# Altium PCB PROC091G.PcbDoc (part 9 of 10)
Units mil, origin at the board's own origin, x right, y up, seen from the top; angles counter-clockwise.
Board outline 4538.11 x 994.94 mil, 8 copper layers (Top Layer, GND1, Sig1, PWR1, PWR2, Sig2, GND2, Bottom Layer), stack 59.155 mil thick; 446 components, 329 nets, 5050 pads, 868 vias.
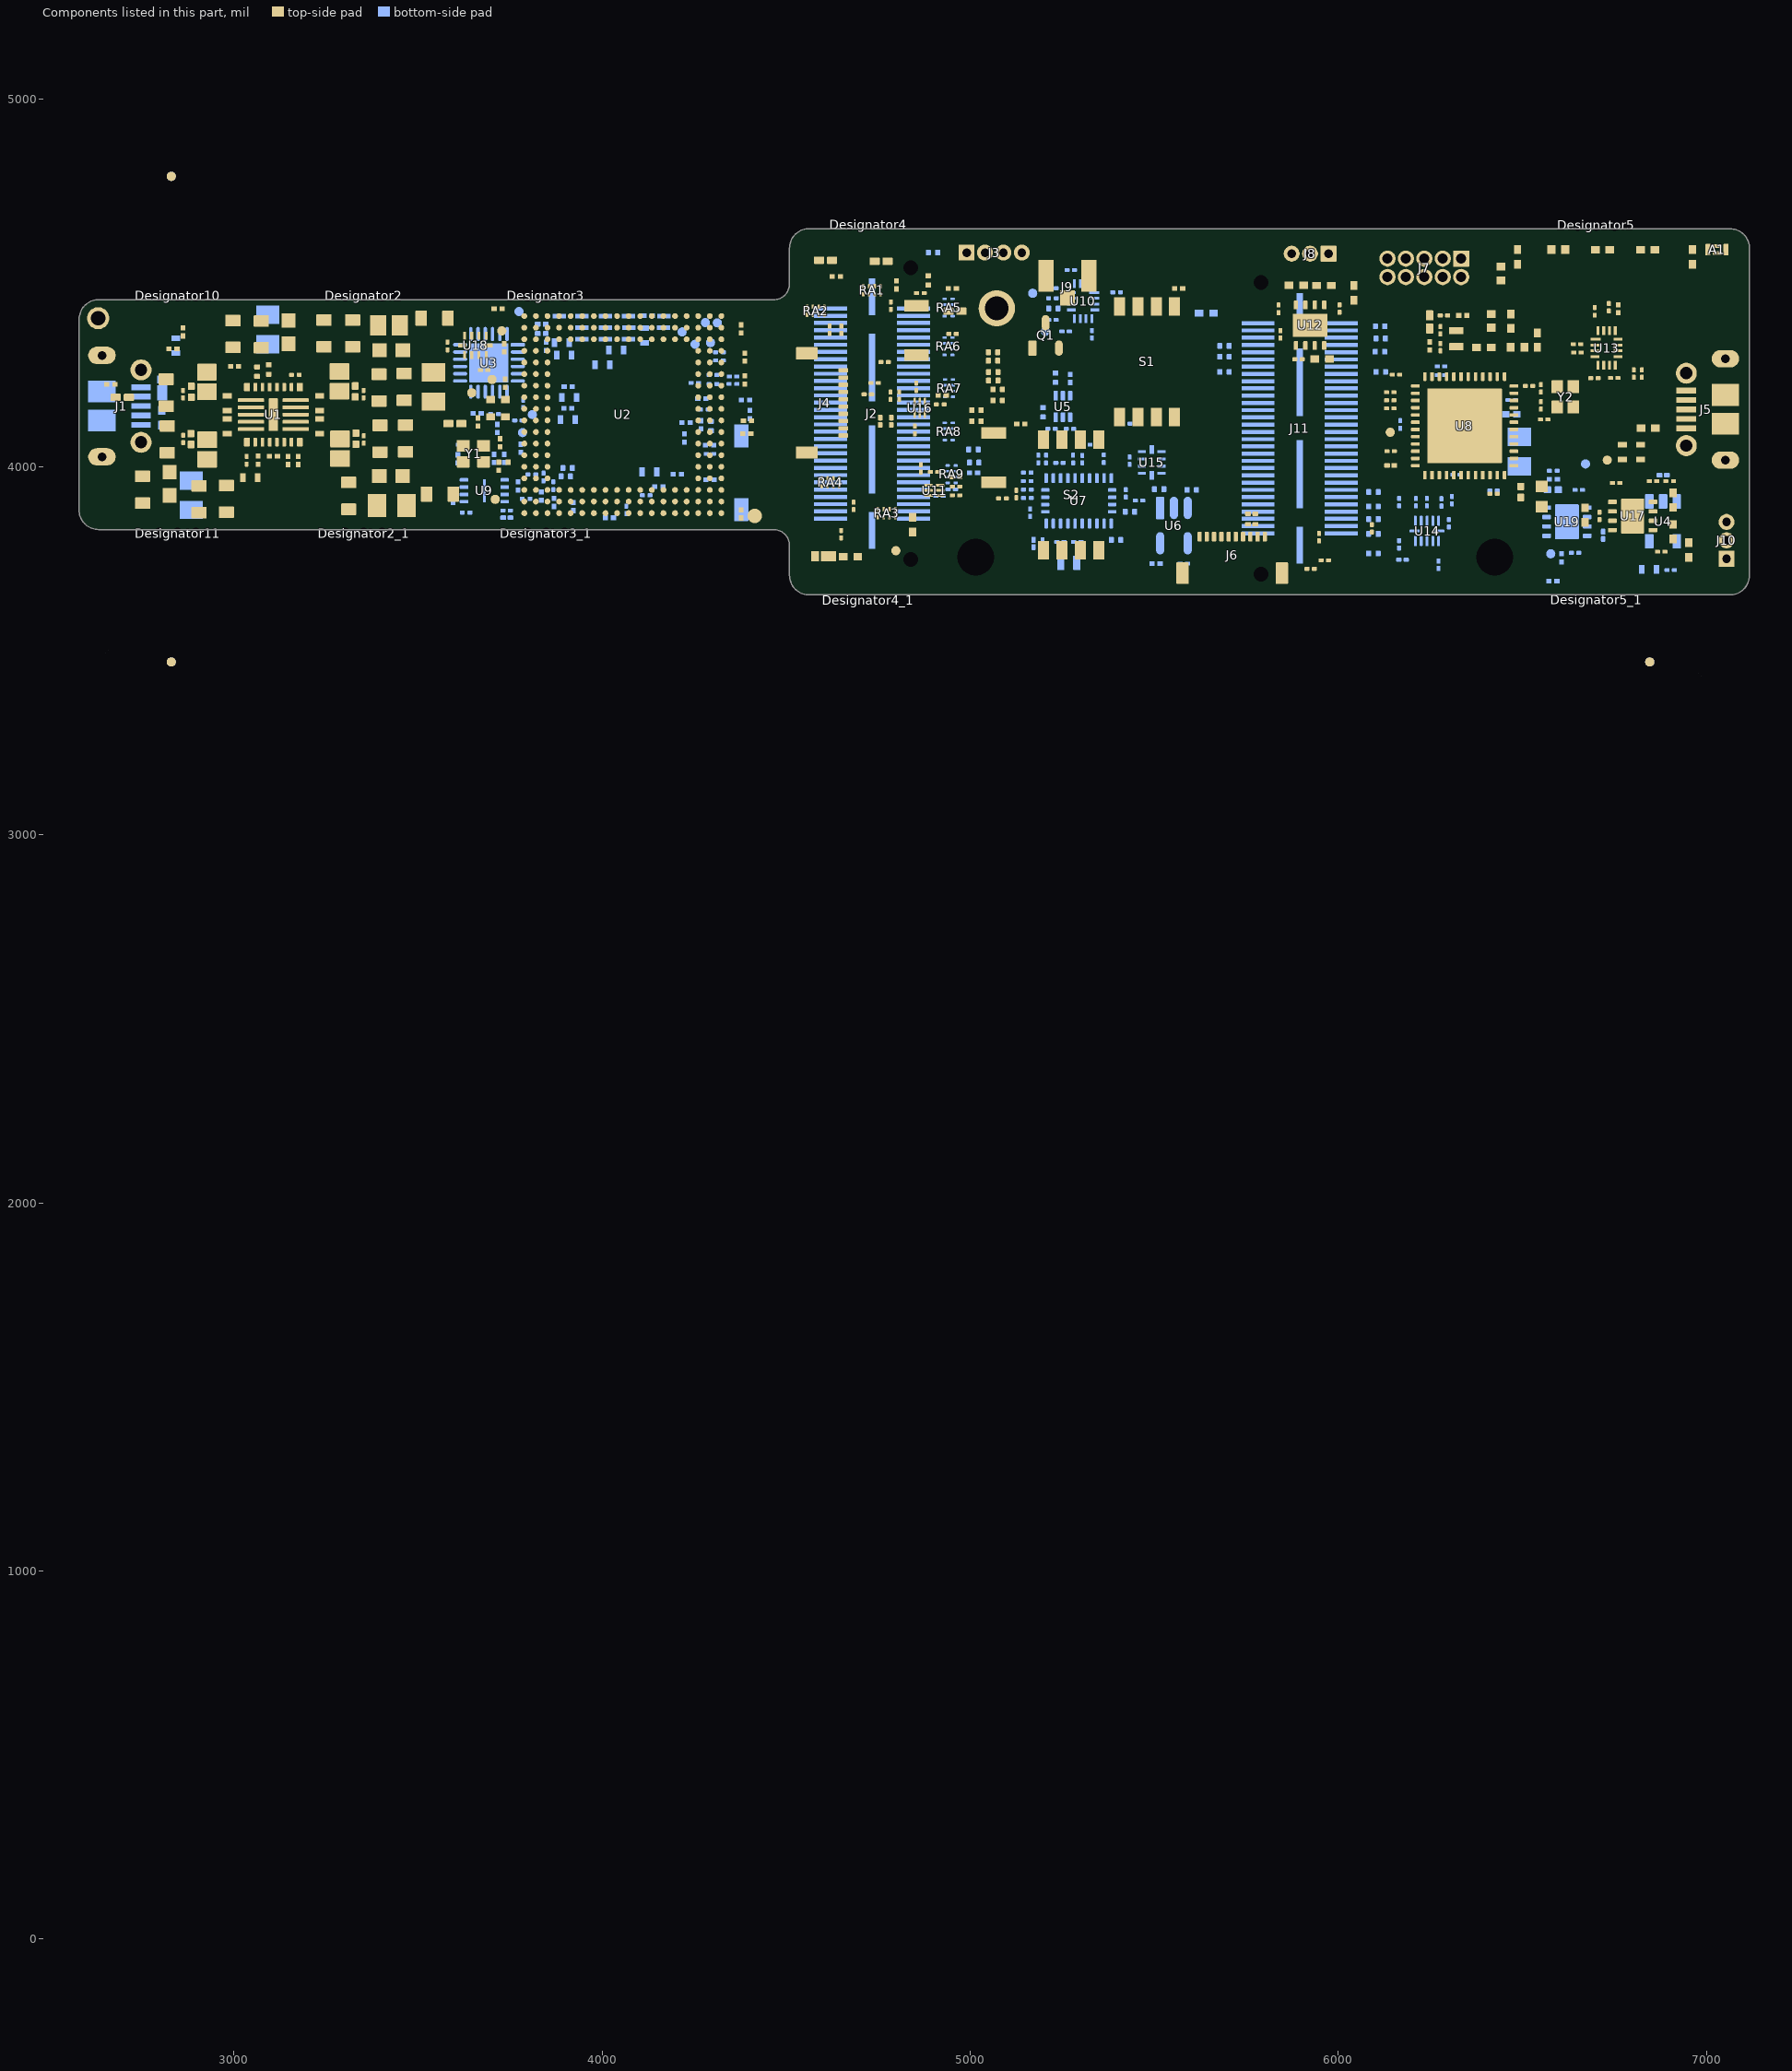
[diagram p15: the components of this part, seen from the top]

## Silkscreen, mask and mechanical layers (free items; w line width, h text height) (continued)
M10 Fab Notes:
  drawing of 275 lines, arcs and shapes, not listed
  text "2" at 3215,8061 h70
  text "1" at 739.84,8036.5 h70
  text "3" at 5724.84,8036.5 h70
  text "4" at 8231.51,8036.5 h70
  text "5" at 10730.5,8036.5 h70
  text "6" at 13235.5,8036.5 h70
  text "A" at -416.5,6893.5 h70
  text "A" at 14383.5,6893.5 h70
  text "DESIGN INFORMATION" at 12391.15,6364.21 h60
  text "3.5" at 12769.13,6238.04 h60
  text "MIN. TRACK WIDTH:" at 11746.59,6232.09 h60
  text "MIL" at 12997.59,6232.09 h60
  text "MIN. CLEARANCE:" at 11746.59,6107.96 h60
  text "3.5" at 12782.83,6107.96 h60
  text "MIL" at 12997.59,6107.96 h60
  text "MIN. VIA PAD SIZE:" at 11746.59,5983.83 h60
  text "18" at 12812.84,5983.84 h60
  text "MIL" at 12997.59,5983.83 h60
  text "0.05mm (2MIL)" at 12441.59,5853.93 h60
  text "MINIMUM ANNULAR RING" at 11417.36,5845.71 h60
  text "EXTERNAL" at 13149.59,5845.71 h60
  text "PER" at 11617.36,5735.58 h60
  text "IPC-D-275 CLASS 2 LEVEL C" at 11837.36,5735.58 h60
  text "MIL, HOLES" at 13325.59,5635.11 h60
  text "+/-" at 12933.13,5626.52 h60
  text "+/-" at 13787.13,5626.52 h60
  text "REGISTRATION TOLERANCES:" at 11417.36,5625.46 h60
  text "METAL" at 12617.13,5625.46 h60
  text "5" at 13193.33,5625.46 h60
  text "3" at 14026.33,5625.46 h60
  text "MIL" at 14142.59,5625.46 h60
  text "HOLE SIZE TOLERANCE (UNLESS OTHERWISE SPECIFIED):" at 11417.36,5527.14 h60
  text "+/-" at 13787.13,5524.27 h60
  text "3" at 14026.33,5523.21 h60
  text "MIL" at 14142.59,5523.2 h60
  text "MATERIAL:" at 11342.59,5385.56 h60
  text "FR-4 High Tg" at 12329.03,5257.03 h60
  text "X" at 12176.59,5254.04 h60
  text "FR-408" at 11763.59,5244.53 h60
  text "OTHER" at 13251.59,5244.53 h60
  text "64 MIL (1.62mm) +/-10%" at 12083.69,5101.5 h60
  text "X" at 11963.59,5099.04 h60
  text "THICKNESS:" at 11417.36,5093.27 h60
  text "OTHER" at 13368.59,5093.27 h60
  text "TOLERANCE:" at 11417.36,4954.96 h60
  text "X" at 12265.59,4954.96 h60
  text "ANSI IPC-6012 TYPE 3 CLASS 2" at 12443.6,4954.96 h60
  text "OTHER +/-" at 12443.59,4810.77 h60
  text "BOW & TWIST:" at 11417.36,4665.58 h60
  text "X" at 12265.59,4665.58 h60
  text "ANSI IPC-6012 TYPE 3 CLASS 2" at 12443.6,4665.58 h60
  text "OTHER +/-" at 12443.59,4518.89 h60
  text "B" at -416.5,4513.5 h70
  text "B" at 14383.5,4513.5 h70
  text "DRILLING:" at 11342.59,4388.27 h60
  text "NC_DRILL FILES" at 13103.59,4283.08 h60
  text "REFERENCE:" at 11417.36,4279.14 h60
  text "X" at 12074.59,4279.04 h60
  text "AS SHOWN" at 12252.59,4279.14 h60
  text "X" at 12975.59,4279.14 h60
  text "OTHER" at 13401.59,4136.89 h60
  text "PTH COPPER THICKNESS:" at 11417.03,4133.36 h60
  text "X" at 12556.27,4133.36 h60
  text "20-30 um" at 12684.27,4133.36 h60
  text "BOARD FINISH:" at 11342.59,3985.76 h60
  text "SILKSCREEN:" at 11497.81,3875.64 h60
  text "X" at 12455.59,3875.64 h60
  text "TOP" at 12572.59,3875.64 h60
  text "X" at 12965.59,3875.64 h60
  text "BOTTOM" at 13083.59,3875.64 h60
  text "SILKSCREEN COLOR:" at 11497.81,3720.45 h60
  text "X" at 12454.59,3720.45 h60
  text "WHITE" at 12572.59,3720.45 h60
  text "OTHER" at 13083.59,3720.45 h60
  text "X" at 12585.59,3577 h60
  text "RED" at 12703.59,3577 h60
  text "OTHER" at 13321.59,3577 h60
  text "SOLDER RESIST COLOR:" at 11497.81,3570.13 h60
  text "X" at 12585.59,3422.75 h60
  text "MATTE" at 12703.59,3422.75 h60
  text "SEMI-GLOSS" at 13321.13,3422.11 h60
  text "IMMERSION GOLD (ENIG)" at 12403.59,3249.98 h60
  text "ENEPIG" at 13741.13,3242.75 h60
  text "SURFACE FINISH:" at 11342.59,3241.75 h60
  text "X" at 12225.59,3241.75 h60
  text "IMM. TIN/SILVER OR EQUIV" at 11672.13,3104.44 h60
  text "OTHER" at 13103.59,3100.5 h60
  text "ARRAY/PANEL:" at 11342.59,2945.12 h60
  text "CUT AND TRIM PER M1 BOARD OUTLINE" at 12403.59,2936.9 h60
  text "X" at 12215,2804 h60
  text "N.C. ROUTE" at 12403.59,2800.94 h60
  text "V. SCORE" at 13269.59,2800.94 h60
  text "CERTIFICATION:" at 11342.59,2671.81 h60
  text "MATERIALS AND WORKMANSHIP FOR ALL PCBS" at 12067.59,2671.81 h60
  text "TO MEET OR EXCEED THE REQUIREMENTS OF:" at 12067.59,2577.75 h60
  text "X" at 11705.1,2449.12 h60
  text "ANSI IPC-A-600F CLASS ->" at 11833.09,2449.12 h60
  text "X" at 13481.1,2449.12 h60
  text "2" at 13591.09,2449.12 h60
  text "1" at 13276.09,2447.62 h60
  text "3" at 13945.09,2447.62 h60
  text "X" at 12517.1,2301.43 h60
  text "RoHS" at 12645.09,2301.43 h60
  text "OTHER" at 13289.49,2301.43 h60
  text "PER ORDER" at 13686.55,2301.43 h60
  text "ALL BOARDS MUST MEET OR EXCEED UL94-V0 REQUIREMENTS." at 11370.13,2147.6 h60
  text "C" at -416.5,2138.5 h70
  text "C" at 14383.5,2138.5 h70
  text "PCB MUST BEAR THE UL94V-0 UL REGISTERED MATERIAL ID NUMBER" at 11370.13,2031.54 h60
  text "ADDITIONAL REQUIREMENTS:" at 11342.59,1862.12 h60
  text "MICROSECTION:" at 11417.36,1754.99 h60
  text "YES" at 12323.09,1754.99 h60
  text "REQUIRED" at 13184.59,1610.66 h60
  text "BARE BOARD ELEC. TEST:" at 11417.36,1607.8 h60
  text "NONE" at 12723.09,1607.8 h60
  text "X" at 13066.59,1607.8 h60
  text "PER ORDER" at 13776.59,1607.8 h60
  text "IMPEDANCE SPECIFICATIONS" at 28.98,1507.25 h82.24
  text "IMPEDANCE SPECIFICATIONS" at 28.98,1507.25 h82.24
  text "XX MIL VIAS REQUIRE NON-CONDUCTIVE FILL AND PLANARIZE" at 11585.51,1402.85 h59
  text "XX MIL VIAS REQUIRE CONDUCTIVE FILL AND PLANARIZE" at 11593.51,1298.88 h60
  text "SL#" at -82.05,1219.4 h82.24
  text "SL#" at -82.05,1219.4 h82.24
  text "TYPE" at 1057,1219.4 h82.24
  text "TYPE" at 1057,1219.4 h82.24
  text "LAYER" at 2257.73,1219.4 h82.24
  text "LAYER" at 2257.73,1219.4 h82.24
  text "TRACEWIDTH(Mils)" at 2944.45,1219.4 h82.24
  text "TRACEWIDTH(Mils)" at 2944.45,1219.4 h82.24
  text "SPACING(Mils)" at 4297.33,1219.4 h82.24
  text "SPACING(Mils)" at 4297.33,1219.4 h82.24
  text "IMPEDANCE(Ohms)" at 5444.61,1219.4 h82.24
  text "IMPEDANCE(Ohms)" at 5444.61,1219.4 h82.24
  text "REF LAYER" at 6711.13,1219.4 h82.24
  text "REF LAYER" at 6711.13,1219.4 h82.24
  text "X" at 11460.14,1142.4 h60
  text "OUTER XX MIL TRACES REQUIRE 50 OHM SINGLE-ENDED IMPEDANCE" at 11592.52,1135.49 h58
  text "L02,L07" at 6867.2,1037.35 h82.24
  text "L1,L8" at 2287.52,1034.24 h82.24
  text "5.50" at 3435.43,1031.07 h82.24
  text "---" at 4689.62,1031.07 h82.24
  text "50" at 5902.69,1031.07 h82.24
  text "MICROSTRIP" at 236.71,1021.53 h82.24
  text "01" at -49.15,1013.79 h82.24
  text "01" at -49.15,1013.79 h82.24
  text "X" at 11462.02,980.86 h60
  text "LAYER 2 & 3 (INNER LAYERS) XX MIL WIDE, XX MIL SPACE / TRACES REQUIRE 100 OHM DIFFERENTIAL IMPEDANCE" at 11584.52,899.78 h60
  text "L07" at 6867.75,897.96 h82.24
  text "4.5" at 4748.83,894.54 h82.24
  text "EDGE COUPLED MICROSTRIP" at 237.95,889.73 h82.24
  text "L8" at 2287.52,890.32 h82.24
  text "4.00" at 3435.43,887.14 h82.24
  text "90" at 5902.69,887.14 h82.24
  text "02" at -48.99,880.83 h82.24
  text "7" at 4794.36,757.36 h82.24
  text "L02,L07" at 6867.2,749.5 h82.24
  text "EDGE COUPLED MICROSTRIP" at 237.95,746.32 h82.24
  text "L1,L8" at 2287.52,746.4 h82.24
  text "4.00" at 3435.43,743.22 h82.24
  text "100" at 5902.69,743.22 h82.24
  text "03" at -48.99,736.91 h82.24
  text "6.1" at 4794.36,613.43 h82.24
  text "L03" at 6867.2,605.58 h82.24
  text "EDGE COUPLED MICROSTRIP" at 237.95,602.4 h82.24
  text "L1" at 2287.52,602.47 h82.24
  text "4.00" at 3435.43,599.3 h82.24
  text "120" at 5902.69,599.3 h82.24
  text "04" at -48.99,592.99 h82.24
  text "L02/04,L05/07" at 6598.31,468.41 h82.24
  text "STRIPLINE" at 233.74,463.86 h82.24
  text "L3,L6" at 2290.85,462.34 h82.24
  text "4.2" at 3435.43,454.49 h82.24
  text "---" at 4689.62,454.49 h82.24
  text "50" at 5902.69,454.49 h82.24
  text "05" at -48.99,449.06 h82.24
  text "L6" at 2290.85,318.41 h82.24
  text "L05/07" at 6755.25,316.53 h82.24
  text "EDGE COUPLED STRIPLINE" at 235.82,316.19 h82.24
  text "6" at 4782.55,314.68 h82.24
  text "4.00" at 3435.43,310.57 h82.24
  text "90" at 5902.69,310.57 h82.24
  text "06" at -48.99,305.14 h82.24
  text "PROJECT TITLE:" at 11343.5,277.5 h45
  text "EDGE COUPLED STRIPLINE" at 233.74,178.91 h82.24
  text "L02/04" at 6755.25,177.53 h82.24
  text "L3" at 2290.85,174.49 h82.24
  text "8" at 4782.55,170.76 h82.24
  text "3.5" at 3435.43,166.65 h82.24
  text "100" at 5902.69,166.65 h82.24
  text "07" at -40.92,163.56 h82.24
  text ".PRJ_Title" at 11393.5,144.17 h70
  text "L1" at 2295.75,39.2 h82.24
  text "14.153" at 3373.6,37.65 h82.24
  text "50" at 5910.92,36.02 h82.24
  text "8.924" at 4721.96,31.51 h82.24
  text "L03" at 6878.95,28.02 h82.24
  text "COPLANAR" at 244.94,26.49 h82.24
  text "08" at -40.92,13.42 h82.24
  text "DESIGNED FOR:" at 11343.5,-23.5 h45
  text ".PRJ_Customer" at 11393.5,-163.5 h70
  text "D" at -416.5,-231.5 h70
  text "D" at 14383.5,-231.5 h70
  text "FILE NAME:" at 11343.5,-323.5 h45
  text ".PCB_File_Name_No_Path" at 11393.5,-443.5 h70
  text "Texas Instruments (TI) and/or its licensors do not warrant the accuracy or completeness of this specification" at 6374,-605.34 h45
  text "ENGINEER:" at 11343.5,-613.5 h45
  text "LAYOUT BY:" at 12848.5,-613.5 h45
  text "or any information contained therein. TI and/or its licensors do not warrant that this design will meet" at 6329.01,-718 h45
  text ".PRJ_Engineer" at 11393.5,-768.49 h70
  text ".PCB_Layout" at 12899,-768.49 h70
  text "the specifications, will be suitable for your application or fit for any particular purpose, or will operate in" at 6329.01,-830.67 h45
  text ".Layer_Name" at 577,-858.49 h60
  text "ALTIUM DESIGNER VERSION:" at 12848.5,-923.5 h45
  text "an implementation. TI and/or its licensors do not warrant that the design is production worthy. You should" at 6329.01,-943.33 h45
  text "completely validate and test your design implementation to confirm the system functionality for your application." at 6374,-1056 h45
  text ".print_Scale" at 11393.5,-1056.83 h70
  text ".Application_BuildNumber" at 12899,-1056.83 h70
  text "1" at 739.84,-1263.5 h70
  text "2" at 3235.5,-1263.5 h70
  text "3" at 5724.84,-1263.5 h70
  text "4" at 8231.51,-1263.5 h70
  text "5" at 10730.5,-1263.5 h70
  text "6" at 13235.5,-1263.5 h70
M11 Gerber Information:
  lines w10: -288.5,-917.67 6311.5,-917.67 ; -288.5,-714.33 6313.5,-714.33 ; -288.5,-511 -288.5,-1121 3716.5,-1121 6313.5,-1121 6313.5,-511 -288,-511 -288,-1121 1287.5,-1121 ; 2176.5,-1121 2176.5,-511 ; 3443.5,-714.33 3443.5,-511 ; 4283.5,-714.33 4283.5,-511 ; 4905.5,-1127.5 4905.5,-924.67
  text "ALL ARTWORK VIEWED FROM TOP SIDE" at -228.5,-655.67 h60
  text "BOARD #:" at 2248,-655.67 h60
  text ".PRJ_Number" at 2793.5,-655.67 h60
  text "REV:" at 3638,-655.67 h60
  text ".PCB_Rev" at 3929.5,-655.67 h60
  text "SVN REV:" at 4476,-655.67 h60
  text ".VersionControl_RevNumber" at 4982,-655.67 h60
  text "LAYER NAME =" at -228.5,-858.49 h60
  text "TID #:" at 2248,-859 h60
  text ".TID" at 2793.5,-859 h60
  text "PLOT NAME =" at -228.5,-1064.34 h60
  text ".plot_File_Name" at 577,-1064.34 h60
  text "GENERATED    :" at 2250,-1064.34 h60
  text ".Print_Date" at 3119.5,-1064.34 h60
  text ".Print_Time" at 3848.5,-1064.34 h60
  text "TEXAS INSTRUMENTS" at 5113,-1064.34 h60
M12 Stackup:
  drawing of 659 lines, arcs and shapes, not listed
  text "Layer" at 7337.32,6608.67 h50.66
  text "Name" at 7686.51,6608.67 h50.66
  text "Material" at 8474.58,6608.67 h50.66
  text "Thickness" at 9203.57,6608.67 h50.66
  text "Constant" at 9755.32,6608.67 h50.66
  text "Board Layer Stack" at 10239.55,6608.67 h50.66
  text "1" at 7337.32,6507.36 h50.66
  text "Top Overlay" at 7686.51,6507.36 h50.66
  text "2" at 7337.32,6406.04 h50.66
  text "Top Solder" at 7686.51,6406.04 h50.66
  text "Solder Resist" at 8474.58,6406.04 h50.66
  text "2.00mil" at 9203.57,6406.04 h50.66
  text "4.4" at 9755.32,6406.04 h50.66
  text "3" at 7337.32,6304.73 h50.66
  text "Top Layer" at 7686.51,6304.73 h50.66
  text "Copper" at 8474.58,6304.73 h50.66
  text "1.85mil" at 9203.57,6304.73 h50.66
  text "4" at 7337.32,6203.42 h50.66
  text "Dielectric1" at 7686.51,6203.42 h50.66
  text "FR-4 High Tg" at 8474.58,6203.42 h50.66
  text "1.46mil" at 9203.57,6203.42 h50.66
  text "3.832" at 9755.32,6203.42 h50.66
  text "5" at 7337.32,6102.11 h50.66
  text "Dielectric 2" at 7686.51,6102.11 h50.66
  text "FR-4 High Tg" at 8474.58,6102.11 h50.66
  text "2.22mil" at 9203.57,6102.11 h50.66
  text "3.832" at 9755.32,6102.11 h50.66
  text "6" at 7337.32,6000.8 h50.66
  text "GND1" at 7686.51,6000.8 h50.66
  text "Copper" at 8474.58,6000.8 h50.66
  text "2.64mil" at 9203.57,6000.8 h50.66
  text "7" at 7337.32,5899.48 h50.66
  text "Dielectric3" at 7686.51,5899.48 h50.66
  text "FR-4 High Tg" at 8474.58,5899.48 h50.66
  text "4.00mil" at 9203.57,5899.48 h50.66
  text "4.4" at 9755.32,5899.48 h50.66
  text "8" at 7337.32,5798.17 h50.66
  text "Sig1" at 7686.51,5798.17 h50.66
  text "Copper" at 8474.58,5798.17 h50.66
  text "1.26mil" at 9203.57,5798.17 h50.66
  text "9" at 7337.32,5696.86 h50.66
  text "Dielectric4" at 7686.51,5696.86 h50.66
  text "FR-4 High Tg" at 8474.58,5696.86 h50.66
  text "3.16mil" at 9203.57,5696.86 h50.66
  text "4.13" at 9755.32,5696.86 h50.66
  text "10" at 7337.32,5595.55 h50.66
  text "Dielectric 5" at 7686.51,5595.55 h50.66
  text "FR-4 High Tg" at 8474.58,5595.55 h50.66
  text "3.16mil" at 9203.57,5595.55 h50.66
  text "4.13" at 9755.32,5595.55 h50.66
  text "11" at 7337.32,5494.24 h50.66
  text "Dielectric 6" at 7686.51,5494.24 h50.66
  text "FR-4 High Tg" at 8474.58,5494.24 h50.66
  text "3.16mil" at 9203.57,5494.24 h50.66
  text "4.13" at 9755.32,5494.24 h50.66
  text "12" at 7337.32,5392.92 h50.66
  text "PWR1" at 7686.51,5392.92 h50.66
  text "Copper" at 8474.58,5392.92 h50.66
  text "2.64mil" at 9203.57,5392.92 h50.66
  text "13" at 7337.32,5291.61 h50.66
  text "Dielectric7" at 7686.51,5291.61 h50.66
  text "FR-4 High Tg" at 8474.58,5291.61 h50.66
  text "8.00mil" at 9203.57,5291.61 h50.66
  text "4.41" at 9755.32,5291.61 h50.66
  text "14" at 7337.32,5190.3 h50.66
  text "PWR2" at 7686.51,5190.3 h50.66
  text "Copper" at 8474.58,5190.3 h50.66
  text "2.64mil" at 9203.57,5190.3 h50.66
  text "15" at 7337.32,5088.99 h50.66
  text "Dielectric8" at 7686.51,5088.99 h50.66
  text "FR-4 High Tg" at 8474.58,5088.99 h50.66
  text "3.18mil" at 9203.57,5088.99 h50.66
  text "4.13" at 9755.32,5088.99 h50.66
  text "16" at 7337.32,4987.67 h50.66
  text "Dielectric 9" at 7686.51,4987.67 h50.66
  text "FR-4 High Tg" at 8474.58,4987.67 h50.66
  text "3.18mil" at 9203.57,4987.67 h50.66
  text "4.13" at 9755.32,4987.67 h50.66
  text "17" at 7337.32,4886.36 h50.66
  text "Dielectric 10" at 7686.51,4886.36 h50.66
  text "FR-4 High Tg" at 8474.58,4886.36 h50.66
  text "3.18mil" at 9203.57,4886.36 h50.66
  text "4.13" at 9755.32,4886.36 h50.66
  text "18" at 7337.32,4785.05 h50.66
  text "Sig2" at 7686.51,4785.05 h50.66
  text "Copper" at 8474.58,4785.05 h50.66
  text "1.26mil" at 9203.57,4785.05 h50.66
  text "19" at 7337.32,4683.74 h50.66
  text "Dielectric11" at 7686.51,4683.74 h50.66
  text "FR-4 High Tg" at 8474.58,4683.74 h50.66
  text "4.00mil" at 9203.57,4683.74 h50.66
  text "4.4" at 9755.32,4683.74 h50.66
  text "20" at 7337.32,4582.43 h50.66
  text "GND2" at 7686.51,4582.43 h50.66
  text "Copper" at 8474.58,4582.43 h50.66
  text "2.64mil" at 9203.57,4582.43 h50.66
  text "21" at 7337.32,4481.11 h50.66
  text "Dielectric12" at 7686.51,4481.11 h50.66
  text "FR-4 High Tg" at 8474.58,4481.11 h50.66
  text "2.22mil" at 9203.57,4481.11 h50.66
  text "3.832" at 9755.32,4481.11 h50.66
  text "22" at 7337.32,4379.8 h50.66
  text "Dielectric 13" at 7686.51,4379.8 h50.66
  text "FR-4 High Tg" at 8474.58,4379.8 h50.66
  text "1.46mil" at 9203.57,4379.8 h50.66
  text "3.832" at 9755.32,4379.8 h50.66
  text "23" at 7337.32,4278.49 h50.66
  text "Bottom Layer" at 7686.51,4278.49 h50.66
  text "Copper" at 8474.58,4278.49 h50.66
  text "1.85mil" at 9203.57,4278.49 h50.66
  text "24" at 7337.32,4177.18 h50.66
  text "Bottom Solder" at 7686.51,4177.18 h50.66
  text "Solder Resist" at 8474.58,4177.18 h50.66
  text "2.00mil" at 9203.57,4177.18 h50.66
  text "4.4" at 9755.32,4177.18 h50.66
  text "25" at 7337.32,4075.87 h50.66
  text "Bottom Overlay" at 7686.51,4075.87 h50.66
  text ".Layer_Name" at 577,-858.49 h60
M13 Component Bodies Top:
  text ".Layer_Name" at 577,-858.49 h60
M14 Component Bodies Bottom:
  text ".Layer_Name" at 577,-858.49 h60
M15 Courtyards Top:
  text ".Layer_Name" at 577,-858.49 h60
M16 Courtyards Bottom:
  text ".Layer_Name" at 577,-858.49 h60
Drill Drawing:
  circle w10: c7611.94,1798.84 r16.58
  circle w10: c7611.94,1798.84 r27.63
  circle w10: c7611.94,555.64 r27.63
  lines w10: 7584.31,666.15 7598.13,666.15 7611.94,652.33 7625.75,666.15 7639.57,666.15 7625.75,679.96 7639.57,693.77 7625.75,693.77 7611.94,707.59 7598.13,693.77 7584.31,693.77 7598.13,679.96 7584.31,666.15 ; 7584.31,790.47 7598.13,790.47 7611.94,776.65 7625.75,790.47 7639.57,790.47 7625.75,804.28 7639.57,818.09 7625.75,818.09 7611.94,831.91 7598.13,818.09 7584.31,818.09 7598.13,804.28 7584.31,790.47 ; 7584.31,914.79 7598.13,914.79 7598.13,900.97 7625.75,900.97 7625.75,914.79 7639.57,914.79 7639.57,942.41 7625.75,942.41 7625.75,956.23 7598.13,956.23 7598.13,942.41 7584.31,942.41 7584.31,914.79 ; 7584.31,1025.29 7611.94,1039.11 7639.57,1025.29 7625.75,1052.92 7639.57,1080.55 7611.94,1066.73 7584.31,1080.55 7598.13,1052.92 7584.31,1025.29 ; 7584.31,1177.24 7611.94,1149.61 7639.57,1177.24 7611.94,1204.87 7584.31,1177.24 ; 7584.31,1273.93 7611.94,1287.75 7639.57,1273.93 7625.75,1301.56 7639.57,1329.19 7611.94,1315.37 7584.31,1329.19 7598.13,1301.56 7584.31,1273.93 ; 7584.31,1453.51 7639.57,1453.51 7611.94,1398.25 7584.31,1453.51 ; 7584.31,1522.57 7584.31,1536.39 7598.13,1550.2 7584.31,1564.01 7584.31,1577.83 7598.13,1577.83 7611.94,1564.01 7625.75,1577.83 7639.57,1577.83 7639.57,1564.01 7625.75,1550.2 7639.57,1536.39 7639.57,1522.57 7625.75,1522.57 7611.94,1536.39 7598.13,1522.57 7584.31,1522.57 ; 7584.31,1646.89 7639.57,1646.89 7639.57,1702.15 7584.31,1702.15 7584.31,1646.89 ; 7584.31,1950.79 7639.57,1950.79 7611.94,1895.53 7584.31,1950.79 ; 7584.31,2019.85 7639.57,2019.85 7639.57,2075.11 7584.31,2075.11 7584.31,2019.85 ; 7595.36,671.67 7603.65,671.67 7611.94,663.38 7620.23,671.67 7628.51,671.67 7620.23,679.96 7628.51,688.25 7620.23,688.25 7611.94,696.54 7603.65,688.25 7595.36,688.25 7603.65,679.96 7595.36,671.67 ; 7595.36,1284.98 7611.94,1293.27 7628.51,1284.98 7620.23,1301.56 7628.51,1318.14 7611.94,1309.85 7595.36,1318.14 7603.65,1301.56 7595.36,1284.98 ; 7595.36,1939.74 7628.51,1939.74 7611.94,1906.58 7595.36,1939.74 ; 7595.36,2030.9 7628.51,2030.9 7628.51,2064.06 7595.36,2064.06 7595.36,2030.9
  lines w12: 7534.22,490.72 11203.47,490.72 ; 7534.22,2106.88 11203.47,2106.88 ; 7872.08,366.4 7872.08,2231.2 ; 8204.08,366.4 8204.08,2231.2 ; 8840.65,366.4 8840.65,2231.2 ; 9099.79,366.4 9099.79,2231.2 ; 9474.95,366.4 9474.95,2231.2 ; 10199.28,366.4 10199.28,2231.2 ; 10728.41,366.4 10728.41,2231.2 ; 7534.22,366.4 11203.47,366.4 11203.47,2231.2 7534.22,2231.2 7534.22,366.4
  text "Symbol" at 7608.81,2144.17 h72
  text "Quantity" at 7909.38,2144.17 h72
  text "Finished Hole Size" at 8241.38,2144.17 h72
  text "Plated" at 8877.94,2144.17 h72
  text "Hole Type" at 9137.08,2144.17 h72
  text "Drill Layer Pair" at 9512.24,2144.17 h72
  text "Hole Tolerance" at 10236.57,2144.17 h72
  text "Hole Length" at 10765.71,2144.17 h72
  text "35" at 7909.38,2019.85 h60
  text "7.87mil" at 8241.38,2019.85 h60
  text "PTH" at 8877.94,2019.85 h60
  text "Round" at 9137.08,2019.85 h60
  text "Top Layer - Bottom Layer" at 9512.24,2019.85 h60
  text "-" at 10765.71,2019.85 h60
  text "142" at 7909.38,1895.53 h60
  text "8.00mil" at 8241.38,1895.53 h60
  text "PTH" at 8877.94,1895.53 h60
  text "Round" at 9137.08,1895.53 h60
  text "Top Layer - Bottom Layer" at 9512.24,1895.53 h60
  text "+/-3.00mil" at 10236.57,1895.53 h60
  text "-" at 10765.71,1895.53 h60
  text "691" at 7909.38,1771.21 h60
  text "8.00mil" at 8241.38,1771.21 h60
  text "PTH" at 8877.94,1771.21 h60
  text "Round" at 9137.08,1771.21 h60
  text "Top Layer - Bottom Layer" at 9512.24,1771.21 h60
  text "-" at 10765.71,1771.21 h60
  text "10" at 7909.38,1646.89 h60
  text "23.62mil" at 8241.38,1646.89 h60
  text "PTH" at 8877.94,1646.89 h60
  text "Round" at 9137.08,1646.89 h60
  text "Top Layer - Bottom Layer" at 9512.24,1646.89 h60
  text "-" at 10765.71,1646.89 h60
  text "4" at 7909.38,1522.57 h60
  text "23.62mil" at 8241.38,1522.57 h60
  text "PTH" at 8877.94,1522.57 h60
  text "Slot" at 9137.08,1522.57 h60
  text "Top Layer - Bottom Layer" at 9512.24,1522.57 h60
  text "51.18mil" at 10765.71,1522.57 h60
  text "10" at 7909.38,1398.25 h60
  text "27.56mil" at 8241.38,1398.25 h60
  text "PTH" at 8877.94,1398.25 h60
  text "Round" at 9137.08,1398.25 h60
  text "Top Layer - Bottom Layer" at 9512.24,1398.25 h60
  text "-" at 10765.71,1398.25 h60
  text "30" at 7909.38,1273.93 h60
  text "32.00mil" at 8241.38,1273.93 h60
  text "NPTH" at 8877.94,1273.93 h60
  text "Round" at 9137.08,1273.93 h60
  text "Top Layer - Bottom Layer" at 9512.24,1273.93 h60
  text "-" at 10765.71,1273.93 h60
  text "4" at 7909.38,1149.61 h60
  text "33.47mil" at 8241.38,1149.61 h60
  text "PTH" at 8877.94,1149.61 h60
  text "Round" at 9137.08,1149.61 h60
  text "Top Layer - Bottom Layer" at 9512.24,1149.61 h60
  text "-" at 10765.71,1149.61 h60
  text "1" at 7909.38,1025.29 h60
  text "40.00mil" at 8241.38,1025.29 h60
  text "PTH" at 8877.94,1025.29 h60
  text "Round" at 9137.08,1025.29 h60
  text "Top Layer - Bottom Layer" at 9512.24,1025.29 h60
  text "-" at 10765.71,1025.29 h60
  text "4" at 7909.38,900.97 h60
  text "40.16mil" at 8241.38,900.97 h60
  text "NPTH" at 8877.94,900.97 h60
  text "Round" at 9137.08,900.97 h60
  text "Top Layer - Bottom Layer" at 9512.24,900.97 h60
  text "-" at 10765.71,900.97 h60
  text "1" at 7909.38,776.65 h60
  text "64.96mil" at 8241.38,776.65 h60
  text "PTH" at 8877.94,776.65 h60
  text "Round" at 9137.08,776.65 h60
  text "Top Layer - Bottom Layer" at 9512.24,776.65 h60
  text "-" at 10765.71,776.65 h60
  text "4" at 7909.38,652.33 h60
  text "88.00mil" at 8241.38,652.33 h60
  text "NPTH" at 8877.94,652.33 h60
  text "Round" at 9137.08,652.33 h60
  text "Top Layer - Bottom Layer" at 9512.24,652.33 h60
  text "+/-3.00mil" at 10236.57,652.33 h60
  text "-" at 10765.71,652.33 h60
  text "2" at 7909.38,528.01 h60
  text "100.00mil" at 8241.38,528.01 h60
  text "NPTH" at 8877.94,528.01 h60
  text "Round" at 9137.08,528.01 h60
  text "Top Layer - Bottom Layer" at 9512.24,528.01 h60
  text "+/-3.00mil" at 10236.57,528.01 h60
  text "-" at 10765.71,528.01 h60
  text "938 Total" at 7909.38,403.69 h60
  text "Slot definitions :" at 7608.81,316.67 h60
  text "Routed Path Length" at 8059.53,316.67 h60
  text "= Calculated from tool start centre position to tool end centre position." at 8599.27,316.67 h60
  text "Hole Length" at 8059.53,266.94 h60
  text "= Routed Path Length + Tool Size = Slot length as defined in the PCB layout" at 8399.47,266.94 h60
  text ".Layer_Name" at 577,-858.49 h60
M17 Embedded Cavity:
  text ".Layer_Name" at 577,-858.49 h60
M18 Embedded Assembly:
  text ".Layer_Name" at 577,-858.49 h60
M19 Embedded Keepout:
  text ".Layer_Name" at 577,-858.49 h60
Mechanical 21:
  drawing of 4281 lines, arcs and shapes, not listed
  text "Works With TI LaunchPad Logo1" at 56021.02,58034.06 h60
  text "Works With TI LaunchPad Logo1" at 56021.02,58034.06 h60
  text "Logo2" at 54657.52,57702.56 h60
  text "Logo2" at 54657.52,57702.56 h60
  text "LOGO3" at 54889.02,57440.06 h60
  text "LOGO3" at 54889.02,57440.06 h60
  text "FID1" at 55092.65,56736 h60
  text "FID1" at 55092.65,56736 h60
  text "FID2" at 55391.65,56726 h60
  text "FID2" at 55391.65,56726 h60
  text "FID6" at 55107.5,56532.5 h60
  text "FID6" at 55107.5,56532.5 h60
  text "FID5" at 55387.5,56532.5 h60
  text "FID5" at 55387.5,56532.5 h60
  text "FID4" at 55668.5,56532.5 h60
  text "FID4" at 55668.5,56532.5 h60
  text "FID3" at 55948.5,56532.5 h60
  text "FID3" at 55948.5,56532.5 h60
  text "ESD Susceptible1" at 56694.52,56524.06 h60
  text "ESD Susceptible1" at 56694.52,56524.06 h60
  text "CAUTION HOT SURFACE1" at 57228.02,56277.06 h60
  text "CAUTION HOT SURFACE1" at 57228.02,56277.06 h60
  text "For evaluation only; not FCC approved for resale." at 54661.42,56095.48 h60 r90
  text "For evaluation only; not FCC approved for resale." at 54661.42,56095.48 h60 r90
  text "Logo1" at 54419.02,55121.06 h60
  text "Logo1" at 54419.02,55121.06 h60
  text "R73" at 57212.4,54825.61 h60
  text "R73" at 57212.4,54825.61 h60
  text "J17" at 56047,54802 h60
  text "J17" at 56047,54802 h60
  text "J4" at 57338,54802 h60
  text "J4" at 57338,54802 h60
  text "J3" at 58017,54787 h60
  text "J3" at 58017,54787 h60
  text "R14" at 57970,54727 h60
  text "R14" at 57970,54727 h60
  text "Q2" at 58016.76,54608.4 h60
  text "Q2" at 58016.76,54608.4 h60
  text "R128" at 57968,54595 h60
  text "R128" at 57968,54595 h60
  text "DS2" at 58182.15,54571 h60
  text "DS2" at 58182.15,54571 h60
  text "R118" at 58197,54456 h60
  text "R118" at 58197,54456 h60
  text "D4" at 58067.44,54360.39 h60
  text "D4" at 58067.44,54360.39 h60
  text "R351" at 57689,54352 h60
  text "R351" at 57689,54352 h60
  text "R350" at 57689,54300 h60
  text "R350" at 57689,54300 h60
  text "R220" at 57803,54206 h60
  text "R220" at 57803,54206 h60
  text "R223" at 57737.75,53914.35 h60
  text "R223" at 57737.75,53914.35 h60
  text "R227" at 57977.49,53913.76 h60
  text "R227" at 57977.49,53913.76 h60
  text "R190" at 56624.85,53824.59 h60
  text "R190" at 56624.85,53824.59 h60
  text "R189" at 56679.85,53824.59 h60
  text "R189" at 56679.85,53824.59 h60
  text "J15" at 57338.02,53806.06 h60
  text "J15" at 57338.02,53806.06 h60
  text "C66" at 56801.85,53741.59 h60
  text "C66" at 56801.85,53741.59 h60
  text "R67" at 57504.63,53724 h60
  text "R67" at 57504.63,53724 h60
  text "C67" at 56534.85,53719.59 h60
  text "R196" at 56534.85,53719.59 h60
  text "C67" at 56534.85,53719.59 h60
  text "R196" at 56534.85,53719.59 h60
  text "R192" at 56584.85,53719.59 h60
  text "R192" at 56584.85,53719.59 h60
  text "R195" at 56634.85,53719.59 h60
  text "R195" at 56634.85,53719.59 h60
  text "R194" at 56684.85,53719.59 h60
  text "R194" at 56684.85,53719.59 h60
  text "R184" at 56801.85,53719.59 h60
  text "R184" at 56801.85,53719.59 h60
  text "R183" at 56854.85,53719.59 h60
  text "R183" at 56854.85,53719.59 h60
  text "R182" at 56904.85,53719.59 h60
  text "R182" at 56904.85,53719.59 h60
  text "R198" at 56397,53660 h60
  text "R198" at 56397,53660 h60
  text "R70" at 57504.63,53624 h60
  text "R70" at 57504.63,53624 h60
  text "U15" at 56578.85,53601.59 h60
  text "U15" at 56578.85,53601.59 h60
  text "R204" at 57113.07,53589.4 h60
  text "R204" at 57113.07,53589.4 h60
  text "R162" at 56492,53581 h60
  text "R162" at 56492,53581 h60
  text "R60" at 57501,53579 h60
  text "R60" at 57501,53579 h60
  text "R161" at 56492,53544 h60
  text "R161" at 56492,53544 h60
  text "R72" at 57727.07,53524 h60
  text "R72" at 57727.07,53524 h60
  text "R199" at 56330,53492.43 h60
  text "R199" at 56330,53492.43 h60
  text "J10" at 55887,53488 h60
  text "J10" at 55887,53488 h60
  text "R64" at 57718,53480 h60
  text "R64" at 57718,53480 h60
  text "R152" at 57977.49,53479.76 h60
  text "R152" at 57977.49,53479.76 h60
  text "C53" at 57216.92,53466.99 h60
  text "C53" at 57216.92,53466.99 h60
  text "L6" at 57283.85,53449.59 h60
  text "L6" at 57283.85,53449.59 h60
  text "C56" at 57111.85,53444.59 h60
  text "C56" at 57111.85,53444.59 h60
  text "C54" at 57163.92,53444.99 h60
  text "C54" at 57163.92,53444.99 h60
  text "R218" at 56330,53437.43 h60
  text "R218" at 56330,53437.43 h60
  text "R76" at 57727.07,53424 h60
  text "R76" at 57727.07,53424 h60
  text "R200" at 56316.85,53386.59 h60
  text "R200" at 56316.85,53386.59 h60
  text "U7" at 57968.92,53371.46 h60
  text "U7" at 57968.92,53371.46 h60
  text "R81" at 57504.02,53324 h60
  text "R81" at 57504.02,53324 h60
  text "R78" at 57727,53324 h60
  text "R78" at 57727,53324 h60
  text "C36" at 56457.8,53322.99 h60
  text "C36" at 56457.8,53322.99 h60
  text "R201" at 57132.85,53319.59 h60
  text "R201" at 57132.85,53319.59 h60
  text "R206" at 56316.85,53286.59 h60
  text "R206" at 56316.85,53286.59 h60
  text "C52" at 57132.85,53269.59 h60
  text "C52" at 57132.85,53269.59 h60
  text "R207" at 56316.85,53236.59 h60
  text "R207" at 56316.85,53236.59 h60
  text "R85" at 57725,53225 h60
  text "R85" at 57725,53225 h60
  text "C51" at 57131.85,53216.59 h60
  text "C51" at 57131.85,53216.59 h60
  text "R208" at 56316.85,53186.59 h60
  text "R208" at 56316.85,53186.59 h60
  text "R394" at 57716,53187 h60
  text "R394" at 57716,53187 h60
  text "R393" at 57755,53185 h60
  text "R393" at 57755,53185 h60
  text "R61" at 57501,53174 h60
  text "R61" at 57501,53174 h60
  text "L5" at 57153.52,53152.08 h60
  text "L5" at 57153.52,53152.08 h60
  text "C59" at 56452,53137 h60
  text "C59" at 56452,53137 h60
  text "R89" at 57732,53111 h60
  text "R89" at 57732,53111 h60
  text "C58" at 56436.57,53084.4 h60
  text "C58" at 56436.57,53084.4 h60
  text "Y2" at 57122.77,53068.99 h60
  text "Y2" at 57122.77,53068.99 h60
  text "C57" at 56972.85,53059.59 h60
  text "C57" at 56972.85,53059.59 h60
  text "C70" at 56589.23,53056.59 h60
  text "C70" at 56589.23,53056.59 h60
  text "C68" at 56737.85,53056.59 h60
  text "C68" at 56737.85,53056.59 h60
  text "J19" at 58033,53057 h60
  text "J19" at 58033,53057 h60
  text "C69" at 56479.07,53037.4 h60
  text "C69" at 56479.07,53037.4 h60
  text "R90" at 57504.63,53024 h60
  text "R90" at 57504.63,53024 h60
  text "R91" at 57727.07,53024 h60
  text "R91" at 57727.07,53024 h60
  text "R150" at 56532,53006 h60
  text "R150" at 56532,53006 h60
  text "C42" at 56567.65,53006 h60
  text "C42" at 56567.65,53006 h60
  text "C30" at 56412.02,52997.6 h60
  text "C30" at 56412.02,52997.6 h60
  text "R95" at 57721,52978 h60
  text "R95" at 57721,52978 h60
  text "R210" at 56479.85,52975.59 h60
  text "R210" at 56479.85,52975.59 h60
  text "R211" at 56550.85,52975.59 h60
  text "R211" at 56550.85,52975.59 h60
  text "R212" at 56580.85,52975.59 h60
  text "R212" at 56580.85,52975.59 h60
  text "R213" at 56631.85,52975.59 h60
  text "R213" at 56631.85,52975.59 h60
  text "R214" at 56682.85,52975.59 h60
  text "R214" at 56682.85,52975.59 h60
  text "R215" at 56733.85,52975.59 h60
  text "R215" at 56733.85,52975.59 h60
  text "R216" at 56784.85,52975.59 h60
  text "R216" at 56784.85,52975.59 h60
  text "R217" at 56833.85,52975.59 h60
  text "R217" at 56833.85,52975.59 h60
  text "U6" at 56399.87,52935.6 h60
  text "U6" at 56399.87,52935.6 h60
  text "R93" at 57504.63,52924 h60
  text "R93" at 57504.63,52924 h60
  text "R92" at 57727.07,52924 h60
  text "R92" at 57727.07,52924 h60
  text "C29" at 56337.49,52919.55 h60
  text "C29" at 56337.49,52919.55 h60
  text "C28" at 56582,52907 h60
  text "C28" at 56582,52907 h60
  text "R187" at 57077,52877 h60
  text "R187" at 57077,52877 h60
  text "R193" at 57181.62,52877 h60
  text "R193" at 57181.62,52877 h60
  text "C55" at 57312,52877 h60
  text "C55" at 57312,52877 h60
  text "U17" at 56762,52840 h60
  text "U17" at 56762,52840 h60
  text "R185" at 57076.48,52827.58 h60
  text "R185" at 57076.48,52827.58 h60
  text "R186" at 57182,52827 h60
  text "R186" at 57182,52827 h60
  text "R181" at 57312,52827 h60
  text "R181" at 57312,52827 h60
  text "R94" at 57504.63,52824 h60
  text "R94" at 57504.63,52824 h60
  text "C62" at 56584.37,52807.06 h60
  text "C62" at 56584.37,52807.06 h60
  text "R304" at 57236,52750 h60
  text "R304" at 57236,52750 h60
  text "R221" at 56507.09,52747.53 h60
  text "R221" at 56507.09,52747.53 h60
  text "U20" at 57186,52741 h60
  text "U20" at 57186,52741 h60
  text "C65" at 56602,52736.38 h60
  text "C65" at 56602,52736.38 h60
  text "C7" at 57154.28,52735.36 h60
  text "C7" at 57154.28,52735.36 h60
  text "J13" at 56412,52725 h60
  text "J13" at 56412,52725 h60
  text "R306" at 57237,52708 h60
  text "R306" at 57237,52708 h60
  text "SW1" at 57858.65,52699 h60
  text "SW1" at 57858.65,52699 h60
  text "U25" at 56979,52678 h60
  text "U25" at 56979,52678 h60
  text "R310" at 57415,52671 h60
  text "R310" at 57415,52671 h60
  text "R151" at 56897,52642 h60
  text "R151" at 56897,52642 h60
  text "R311" at 57415,52636 h60
  text "R311" at 57415,52636 h60
  text "S7" at 56399,52624 h60
  text "S7" at 56399,52624 h60
  text "R301" at 57372,52599 h60
  text "R301" at 57372,52599 h60
  text "C73" at 56262.62,52569.53 h60
  text "C73" at 56262.62,52569.53 h60
  text "R338" at 56787.37,52555.06 h60
  text "R338" at 56787.37,52555.06 h60
  text "U26" at 56919.12,52539.06 h60
  text "U26" at 56919.12,52539.06 h60
  text "R209" at 56801,52497 h60
  text "R209" at 56801,52497 h60
  text "S10" at 56399,52494 h60
  text "S10" at 56399,52494 h60
  text "C27" at 56283.06,52418 h60
  text "C27" at 56283.06,52418 h60
  text "C50" at 55666,52407 h60
  text "C50" at 55666,52407 h60
  text "S5" at 56399,52381 h60
  text "S5" at 56399,52381 h60
  text "U28" at 56817,52365 h60
  text "U28" at 56817,52365 h60
  text "J14" at 57878.02,52346.06 h60
  text "J14" at 57878.02,52346.06 h60
  text "R24" at 56760,52338 h60
  text "R24" at 56760,52338 h60
  text "U11" at 57728.34,52328.92 h60
  text "U11" at 57728.34,52328.92 h60
  text "R339" at 56204.5,52306.5 h60
  text "R339" at 56204.5,52306.5 h60
  text "S6" at 56399,52288 h60
  text "S6" at 56399,52288 h60
  text "R25" at 56350,52285 h60
  text "R25" at 56350,52285 h60
  text "R16" at 56048,52270.5 h60
  text "R16" at 56048,52270.5 h60
  text "C72" at 55979,52269.62 h60
  text "C72" at 55979,52269.62 h60
  text "R173" at 57089,52231 h60
  text "R173" at 57089,52231 h60
  text "C94" at 56205,52229 h60
  text "C94" at 56205,52229 h60
  text "R18" at 56764,52229 h60
  text "R18" at 56764,52229 h60
  text "U33" at 56923.22,52200.19 h60
  text "U33" at 56923.22,52200.19 h60
  text "U19" at 57072,52191 h60
  text "U19" at 57072,52191 h60
  text "R175" at 57160.32,52177.62 h60
  text "R175" at 57160.32,52177.62 h60
  text "S11" at 56399,52175 h60
  text "S11" at 56399,52175 h60
  text "R41" at 56339.02,52156.06 h60
  text "R41" at 56339.02,52156.06 h60
  text "SW2" at 58116.65,52147 h60
  text "SW2" at 58116.65,52147 h60
  text "R19" at 56771,52133 h60
  text "R19" at 56771,52133 h60
  text "C112" at 56048,52118 h60
  text "C112" at 56048,52118 h60
  text "C117" at 56270.24,52116 h60
  text "C117" at 56270.24,52116 h60
  text "C49" at 57105,52095 h60
  text "C49" at 57105,52095 h60
  text "R180" at 57145,52095 h60
  text "R180" at 57145,52095 h60
  text "R172" at 57063,52089 h60
  text "R172" at 57063,52089 h60
  text "LBL1" at 58550.37,52085.06 h60
  text "LBL1" at 58550.37,52085.06 h60
  text "J9" at 55627.11,52069.11 h60
  text "J9" at 55627.11,52069.11 h60
  text "S3" at 56339,52044 h60
  text "S3" at 56339,52044 h60
  text "R8" at 56993,52019 h60
  text "R8" at 56993,52019 h60
  text "U1" at 56726,52004 h60
  text "U1" at 56726,52004 h60
  text "R229" at 56004.36,51991.59 h60
  text "R229" at 56004.36,51991.59 h60
  text "C2" at 56692,51990.69 h60
  text "C2" at 56692,51990.69 h60
  text "C4" at 57710.2,51977.88 h60
  text "C4" at 57710.2,51977.88 h60
  text "U32" at 56133,51977 h60
  text "U32" at 56133,51977 h60
  text "R1" at 57048,51952 h60
  text "R1" at 57048,51952 h60
  text "R117" at 57862.62,51943.53 h60
  text "R117" at 57862.62,51943.53 h60
  text "R144" at 56003.74,51942.05 h60
  text "R144" at 56003.74,51942.05 h60
  text "R3" at 56919,51937 h60
  text "R3" at 56919,51937 h60
  text "Q1" at 57946.65,51928 h60
  text "Q1" at 57946.65,51928 h60
  text "R261" at 57830.74,51910.17 h60
  text "R261" at 57830.74,51910.17 h60
  text "R54" at 56005,51891 h60
  text "R54" at 56005,51891 h60
  text "DS1" at 58120,51890 h60
  text "DS1" at 58120,51890 h60
  text "C76" at 56572.13,51859.91 h60
  text "C76" at 56572.13,51859.91 h60
  text "S1" at 57770.72,51851 h60
  text "S1" at 57770.72,51851 h60
  text "L7" at 56445.37,51847.06 h60
  text "L7" at 56445.37,51847.06 h60
  text "R270" at 56005,51841 h60
  text "R270" at 56005,51841 h60
  text "R6" at 57000,51841 h60
  text "R6" at 57000,51841 h60
  text "J28" at 56344.97,51821.39 h60
  text "J28" at 56344.97,51821.39 h60
  text "R260" at 57790,51821 h60
  text "R260" at 57790,51821 h60
  text "C111" at 56141.07,51805 h60
  text "C111" at 56141.07,51805 h60
  text "U3" at 56906,51797 h60
  text "U3" at 56906,51797 h60
  text "U12" at 56512.86,51794.81 h60
  text "U12" at 56512.86,51794.81 h60
  text "R269" at 56005,51791 h60
  text "R269" at 56005,51791 h60
  text "R113" at 56205.45,51785.73 h60
  text "R113" at 56205.45,51785.73 h60
  text "J1" at 57964,51782 h60
  text "J1" at 57964,51782 h60
  text "R268" at 56005,51736 h60
  text "R268" at 56005,51736 h60
  text "H2" at 59278.02,51732.06 h60
  text "H2" at 59278.02,51732.06 h60
  text "R256" at 56477.37,51691.06 h60
  text "R256" at 56477.37,51691.06 h60
  text "R30" at 56005,51686 h60
  text "R30" at 56005,51686 h60
  text "R321" at 57316,51648 h60
  text "R321" at 57316,51648 h60
  text "R29" at 56005,51636 h60
  text "R29" at 56005,51636 h60
  text "R324" at 57296,51608 h60
  text "R324" at 57296,51608 h60
  text "Logo4" at 58802.02,51607.06 h60
  text "Logo4" at 58802.02,51607.06 h60
  text "U23" at 57286.85,51605.4 h60
  text "U23" at 57286.85,51605.4 h60
  text "C3" at 57912.37,51605.06 h60
  text "C3" at 57912.37,51605.06 h60
  text "C26" at 57052.91,51598.66 h60
  text "C26" at 57052.91,51598.66 h60
  text "H1" at 58428.02,51592.06 h60
  text "H1" at 58428.02,51592.06 h60
  text "R28" at 56005,51581 h60
  text "R28" at 56005,51581 h60
  text "R313" at 56661.74,51578.44 h60
  text "R313" at 56661.74,51578.44 h60
  text "R331" at 57329.82,51571.99 h60
  text "R331" at 57329.82,51571.99 h60
  text "D11" at 56775.76,51570.07 h60
  text "D11" at 56775.76,51570.07 h60
  text "R291" at 56531,51569 h60
  text "R291" at 56531,51569 h60
  text "C81" at 57580,51554 h60
  text "C81" at 57580,51554 h60
  text "R317" at 57316.07,51536.47 h60
  text "R317" at 57316.07,51536.47 h60
  text "R27" at 56005,51531 h60
  text "R27" at 56005,51531 h60
  text "L9" at 56729,51530 h60
  text "L9" at 56729,51530 h60
  text "P1" at 56364.86,51510 h60
  text "P1" at 56364.86,51510 h60
  text "R396" at 56236,51508 h60
  text "R396" at 56236,51508 h60
  text "R332" at 57303,51501 h60
  text "R332" at 57303,51501 h60
  text "R397" at 56156,51488 h60
  text "R397" at 56156,51488 h60
  text "R21" at 56005,51481 h60
  text "R21" at 56005,51481 h60
  text "C120" at 56233,51472 h60
  text "C120" at 56233,51472 h60
  text "U30" at 56169,51440 h60
  text "U30" at 56169,51440 h60
  text "R20" at 56005,51431 h60
  text "R20" at 56005,51431 h60
  text "R271" at 57433.29,51414.06 h60
  text "R271" at 57433.29,51414.06 h60
  text "C82" at 57571,51411 h60
  text "C82" at 57571,51411 h60
  text "R395" at 56133.32,51388.04 h60
  text "R395" at 56133.32,51388.04 h60
  text "R246" at 56005,51381 h60
  text "R246" at 56005,51381 h60
  text "C78" at 57741,51368 h60
  text "C78" at 57741,51368 h60
  text "J2" at 57964,51337 h60
  text "J2" at 57964,51337 h60
  text "R243" at 56005,51331 h60
  text "R243" at 56005,51331 h60
  text "L8" at 57711,51315 h60
  text "L8" at 57711,51315 h60
  text "R309" at 56935.21,51298.07 h60
  text "R309" at 56935.21,51298.07 h60
  text "U13" at 57467,51295 h60
  text "U13" at 57467,51295 h60
  text "C88" at 56223,51294 h60
  text "C88" at 56223,51294 h60
  text "C108" at 56561,51275 h60
  text "C108" at 56561,51275 h60
  text "U29" at 56752,51266 h60
  text "U29" at 56752,51266 h60
  text "J27" at 56378.3,51228.62 h60
  text "J27" at 56378.3,51228.62 h60
  text "R115" at 56222.08,51202.58 h60
  text "R115" at 56222.08,51202.58 h60
  text "C99" at 57036,51199 h60
  text "C99" at 57036,51199 h60
  text "H3" at 59278.02,51192.06 h60
  text "H3" at 59278.02,51192.06 h60
  text "C100" at 56947,51182 h60
  text "C100" at 56947,51182 h60
  text "H4" at 59658.02,51182.06 h60
  text "H4" at 59658.02,51182.06 h60
  text "H5" at 60008.02,51182.06 h60
  text "H5" at 60008.02,51182.06 h60
  text "U31" at 56061,51181 h60
  text "U31" at 56061,51181 h60
  text "C102" at 56496,51175 h60
  text "C102" at 56496,51175 h60
  text "H6" at 60368.02,51172.06 h60
  text "H6" at 60368.02,51172.06 h60
  text "C103" at 56629,51171 h60
  text "C103" at 56629,51171 h60
  text "C87" at 57290,51136 h60
  text "C87" at 57290,51136 h60
  text "R318" at 58884.02,51117.68 h60
  text "R318" at 58884.02,51117.68 h60
  text "R315" at 58534.02,51114.06 h60
  text "R315" at 58534.02,51114.06 h60
  text "C91" at 57811,51090 h60
  text "C91" at 57811,51090 h60
  text "R131" at 55699.43,51041.54 h60
  text "R131" at 55699.43,51041.54 h60
  text "C97" at 56692.79,51024.94 h60
  text "C97" at 56692.79,51024.94 h60
  text "C109" at 56067,50998 h60
  text "C109" at 56067,50998 h60
  text "R140" at 55967.43,50996.54 h60
  text "R140" at 55967.43,50996.54 h60
  text "R133" at 55707.43,50987.54 h60
  text "R133" at 55707.43,50987.54 h60
  text "R139" at 55829.43,50987.54 h60
  text "R139" at 55829.43,50987.54 h60
  text "C79" at 57637.52,50972.56 h60
  text "C79" at 57637.52,50972.56 h60
  text "R135" at 55624.43,50940.54 h60
  text "R135" at 55624.43,50940.54 h60
  text "R136" at 55745.43,50940.54 h60
  text "R136" at 55745.43,50940.54 h60
  text "R141" at 55876.43,50932.54 h60
  text "R141" at 55876.43,50932.54 h60
  text "R134" at 55707.43,50906.54 h60
  text "R134" at 55707.43,50906.54 h60
  text "R138" at 55829.43,50906.54 h60
  text "R138" at 55829.43,50906.54 h60
  text "R132" at 55625.43,50905.54 h60
  text "R132" at 55625.43,50905.54 h60
  text "R137" at 55745.43,50905.54 h60
  text "R137" at 55745.43,50905.54 h60
  text "R143" at 55876.43,50897.54 h60
  text "R143" at 55876.43,50897.54 h60
  text "R116" at 57765.62,50891.53 h60
  text "R116" at 57765.62,50891.53 h60
  text "P7" at 57484.37,50880.06 h60
  text "P7" at 57484.37,50880.06 h60
  text "P3" at 57606.37,50880.06 h60
  text "P3" at 57606.37,50880.06 h60
  text "TP1" at 57933.94,50875.28 h60
  text "TP1" at 57933.94,50875.28 h60
  text "D14" at 58099.72,50838 h60
  text "D14" at 58099.72,50838 h60
  text "P4" at 55566,50798.61 h60
  text "P4" at 55566,50798.61 h60
  text "J18" at 55787.63,50773.94 h60
  text "J18" at 55787.63,50773.94 h60
  text "J20" at 56602.63,50773.94 h60
  text "J20" at 56602.63,50773.94 h60
  text "P2" at 57944,50712.02 h60
  text "P2" at 57944,50712.02 h60
  text "C23" at 57473,50628 h60
  text "C23" at 57473,50628 h60
  text "F1" at 57792,50601 h60
  text "F1" at 57792,50601 h60
  text "P5" at 55566,50598.75 h60
  text "P5" at 55566,50598.75 h60
  text "J16" at 55938,50552 h60
  text "J16" at 55938,50552 h60
  text "R142" at 56107.74,50443.95 h60 r90
  text "R142" at 56107.74,50443.95 h60 r90
  text "P6" at 55566,50401 h60
  text "P6" at 55566,50401 h60
  text "D1" at 57757.37,50398.06 h60
  text "D1" at 57757.37,50398.06 h60
  text "D8" at 56409.81,50257.81 h60
  text "D8" at 56409.81,50257.81 h60
  text "DS4" at 55968,50257 h60
  text "DS4" at 55968,50257 h60
  text "DS3" at 56037,50256 h60
  text "DS3" at 56037,50256 h60
  text "D6" at 56255,50256 h60
  text "D6" at 56255,50256 h60
  text "D10" at 55995,50254.54 h60
  text "D10" at 55995,50254.54 h60
  text "D9" at 56115,50254.54 h60
  text "D9" at 56115,50254.54 h60
  text "D5" at 56185,50254.54 h60
  text "D5" at 56185,50254.54 h60
  text "D7" at 56329.19,50254.54 h60
  text "D7" at 56329.19,50254.54 h60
